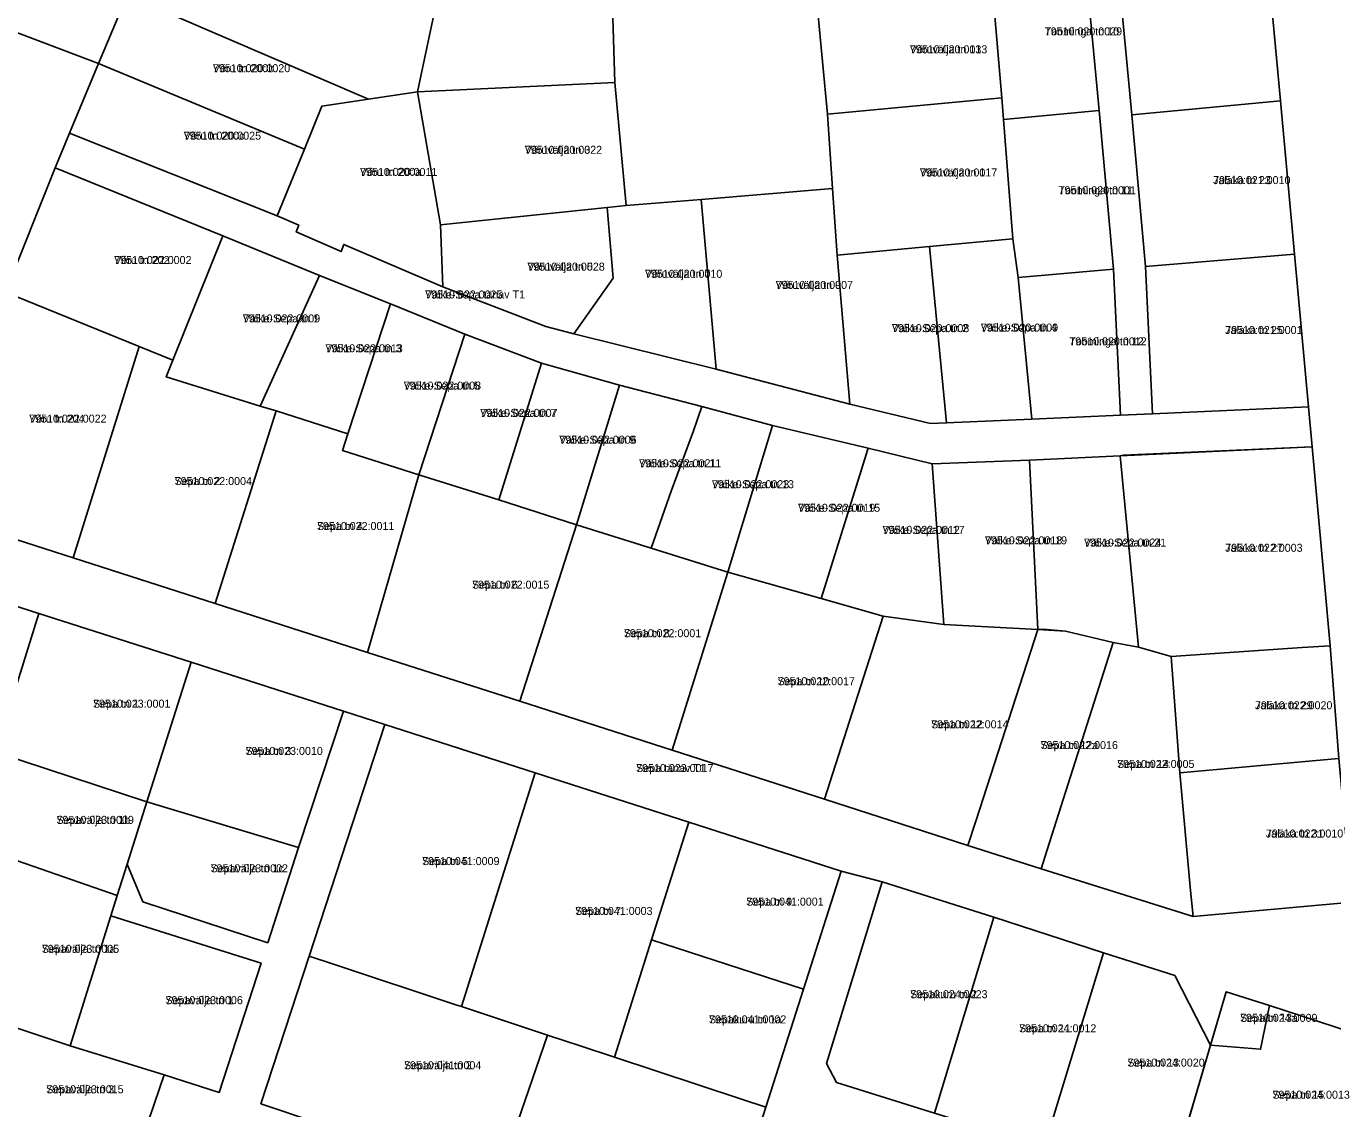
# Model space of a CAD drawing. Extents: x 643847 to 663718, y 6468443 to 6482775.
# Drawn here: x 659148.1 to 659393.1, y 6470944.7 to 6471147.7 of the extents above; entities that cross this region are included whole.
import ezdxf

# ---------------------------------------------------------------- set-up
doc = ezdxf.new("R2010")
doc.units = 0
for name, color, linetype in [('L_AADRESS', 7, 'Continuous'), ('PIIR', 7, 'Continuous'), ('TUNNUS', 7, 'Continuous')]:
    doc.layers.add(name, color=color, linetype=linetype)

msp = doc.modelspace()

# ---------------------------------------------------------------- linework, layer by layer
at = {"layer": 'PIIR'}
for points in [[(659341.82, 6471281.22), (659344.26, 6471253.81), (659347.37, 6471219.61), (659349.7, 6471192.1), (659352.5, 6471162.11), (659355.44, 6471131.04), (659357.98, 6471102.6), (659359.29, 6471075.01), (659353.29, 6471074.75), (659352, 6471102.11), (659349.29, 6471131.84), (659346.5, 6471161.7), (659344.95, 6471178.32), (659343.73, 6471191.56), (659341.19, 6471221.27), (659338.38, 6471251.03), (659335.78, 6471280.87)], [(659215.12, 6471272.69), (659207.74, 6471253.86), (659199.84, 6471234.85), (659192.92, 6471216.05), (659183.17, 6471191.52), (659179.27, 6471182.28), (659167.08, 6471153.51), (659161.74, 6471140.7), (659143.9, 6471147.43), (659146, 6471152.81), (659159.33, 6471183.88), (659165.84, 6471200.73), (659172.33, 6471217.52), (659190.04, 6471263.38)], [(659394.21, 6471010.38), (659392.61, 6471031.55), (659389.2, 6471068.83), (659388.52, 6471076.29), (659385.89, 6471104.93), (659383.27, 6471133.67), (659380.44, 6471164.64), (659377.72, 6471194.35), (659375.15, 6471222.47), (659372.07, 6471256.11), (659393.48, 6471257.44)], [(659296.51, 6471150.91), (659298.36, 6471131.19), (659299.32, 6471117.27), (659274.71, 6471115.16), (659260.61, 6471114.03), (659258.52, 6471137.09), (659257.67, 6471163.44)], [(659059.58, 6470932.21), (659070.24, 6470963.44), (659077.19, 6470983.79), (659085.91, 6471009.34), (659093.99, 6471033), (659101.62, 6471055.42), (659110.68, 6471064.49), (659132.41, 6471119.15), (659111.06, 6471126.27), (659112.87, 6471130.38), (659113.94, 6471132.87), (659134.67, 6471124.72), (659143.9, 6471147.43), (659161.74, 6471140.7), (659156.3, 6471127.64), (659153.58, 6471121.12), (659144.31, 6471097.84), (659128.09, 6471059.03), (659124.04, 6471046.08), (659115.81, 6471022.07), (659109.61, 6471003.78), (659099.59, 6470975.6), (659093.31, 6470956.47), (659086.53, 6470937.12)], [(659130.31, 6471056.6), (659156.94, 6471048.04), (659183.57, 6471039.44), (659212.14, 6471030.3), (659240.68, 6471021.12), (659269.23, 6471011.94), (659297.78, 6471002.75), (659324.71, 6470994.08), (659338.42, 6470989.73), (659366.89, 6470980.81), (659396.67, 6470983.46)], [(659399.57, 6470958.09), (659381.25, 6470964.1), (659373.12, 6470966.68), (659370.19, 6470956.69), (659363.46, 6470969.73), (659350.11, 6470973.96), (659329.56, 6470980.68), (659308.62, 6470987.26), (659300.94, 6470989.29), (659272.39, 6470998.46), (659243.57, 6471007.71), (659215.36, 6471016.77), (659207.64, 6471019.25), (659179.08, 6471028.43), (659150.5, 6471037.59), (659124.04, 6471046.08)], [(659281.07, 6470926.97), (659286.84, 6470945.06), (659293.89, 6470967.18), (659300.94, 6470989.29), (659308.62, 6470987.26), (659298.18, 6470953.21), (659300.07, 6470949.66), (659318.43, 6470943.89)]]:
    msp.add_lwpolyline(points, dxfattribs=at)
for points in [[(659179.27, 6471182.28), (659227.18, 6471162.23), (659221.51, 6471135.38), (659212.32, 6471134), (659167.08, 6471153.51)], [(659257.67, 6471163.44), (659258.52, 6471137.09), (659221.51, 6471135.38), (659227.18, 6471162.23)], [(659383.27, 6471133.67), (659355.44, 6471131.04), (659352.5, 6471162.11), (659380.44, 6471164.64)], [(659346.5, 6471161.7), (659349.29, 6471131.84), (659331.36, 6471130.16), (659331.04, 6471134.25), (659329.39, 6471153.98), (659328.88, 6471160.06)], [(659167.08, 6471153.51), (659212.32, 6471134), (659203.59, 6471132.69), (659200.33, 6471124.59), (659161.74, 6471140.7)], [(659296.51, 6471150.91), (659329.39, 6471153.98), (659331.04, 6471134.25), (659298.36, 6471131.19)], [(659161.74, 6471140.7), (659200.33, 6471124.59), (659195.19, 6471112.11), (659156.3, 6471127.64)], [(659260.61, 6471114.03), (659257.09, 6471113.66), (659225.8, 6471110.41), (659221.51, 6471135.38), (659258.52, 6471137.09)], [(659207.7, 6471106.76), (659207.2, 6471105.43), (659198.79, 6471109.11), (659199.26, 6471110.36), (659195.19, 6471112.11), (659200.33, 6471124.59), (659203.59, 6471132.69), (659212.32, 6471134), (659221.51, 6471135.38), (659225.8, 6471110.41), (659226.29, 6471098.81)], [(659298.36, 6471131.19), (659331.04, 6471134.25), (659331.36, 6471130.16), (659333.14, 6471107.83), (659317.52, 6471106.37), (659300.19, 6471104.75), (659299.32, 6471117.27)], [(659385.89, 6471104.93), (659357.98, 6471102.6), (659355.44, 6471131.04), (659383.27, 6471133.67)], [(659352, 6471102.11), (659334.1, 6471100.55), (659333.14, 6471107.83), (659331.36, 6471130.16), (659349.29, 6471131.84)], [(659185.02, 6471108.37), (659153.58, 6471121.12), (659156.3, 6471127.64), (659195.19, 6471112.11), (659199.26, 6471110.36), (659198.79, 6471109.11), (659207.2, 6471105.43), (659207.7, 6471106.76), (659226.29, 6471098.81), (659245.54, 6471091.41), (659250.81, 6471090.03), (659277.49, 6471083.38), (659302.59, 6471076.85), (659317.7, 6471073.17), (659320.7, 6471073.31), (659336.68, 6471074.01), (659353.29, 6471074.75), (659359.29, 6471075.01), (659388.52, 6471076.29), (659389.2, 6471068.83), (659353.81, 6471067.25), (659353.24, 6471067.14), (659336.25, 6471066.32), (659317.97, 6471065.62), (659305.99, 6471068.6), (659288.07, 6471072.81), (659274.79, 6471076.36), (659259.4, 6471080.38), (659244.77, 6471084.49), (659230.38, 6471089.97), (659216.47, 6471095.61), (659203.12, 6471100.95)], [(659153.58, 6471121.12), (659185.02, 6471108.37), (659175.65, 6471085.06), (659169.35, 6471087.6), (659144.31, 6471097.84)], [(659299.32, 6471117.27), (659300.19, 6471104.75), (659302.59, 6471076.85), (659277.49, 6471083.38), (659274.71, 6471115.16)], [(659250.81, 6471090.03), (659245.54, 6471091.41), (659226.29, 6471098.81), (659225.8, 6471110.41), (659257.09, 6471113.66), (659258.17, 6471100.45)], [(659250.81, 6471090.03), (659258.17, 6471100.45), (659257.09, 6471113.66), (659260.61, 6471114.03), (659274.71, 6471115.16), (659277.49, 6471083.38)], [(659203.12, 6471100.95), (659192.04, 6471076.45), (659174.41, 6471081.92), (659175.65, 6471085.06), (659185.02, 6471108.37)], [(659317.7, 6471073.17), (659302.59, 6471076.85), (659300.19, 6471104.75), (659317.52, 6471106.37), (659320.7, 6471073.31)], [(659320.7, 6471073.31), (659317.52, 6471106.37), (659333.14, 6471107.83), (659334.1, 6471100.55), (659336.68, 6471074.01)], [(659388.52, 6471076.29), (659359.29, 6471075.01), (659357.98, 6471102.6), (659385.89, 6471104.93)], [(659353.29, 6471074.75), (659336.68, 6471074.01), (659334.1, 6471100.55), (659352, 6471102.11)], [(659216.47, 6471095.61), (659208.46, 6471071.25), (659195.03, 6471075.6), (659192.04, 6471076.45), (659203.12, 6471100.95)], [(659144.31, 6471097.84), (659169.35, 6471087.6), (659156.94, 6471048.04), (659130.31, 6471056.6), (659128.09, 6471059.03)], [(659230.38, 6471089.97), (659221.77, 6471063.59), (659207.48, 6471068.13), (659208.46, 6471071.25), (659216.47, 6471095.61)], [(659244.77, 6471084.49), (659236.77, 6471058.91), (659221.77, 6471063.59), (659230.38, 6471089.97)], [(659156.94, 6471048.04), (659169.35, 6471087.6), (659175.65, 6471085.06), (659174.41, 6471081.92), (659192.04, 6471076.45), (659195.03, 6471075.6), (659183.57, 6471039.44)], [(659259.4, 6471080.38), (659251.31, 6471054.21), (659236.77, 6471058.91), (659244.77, 6471084.49)], [(659274.79, 6471076.36), (659273.27, 6471071.8), (659269.04, 6471060.54), (659265.32, 6471049.84), (659251.31, 6471054.21), (659259.4, 6471080.38)], [(659183.57, 6471039.44), (659195.03, 6471075.6), (659208.46, 6471071.25), (659207.48, 6471068.13), (659221.77, 6471063.59), (659212.14, 6471030.3)], [(659274.79, 6471076.36), (659288.07, 6471072.81), (659279.71, 6471045.36), (659265.32, 6471049.84), (659269.04, 6471060.54), (659273.27, 6471071.8)], [(659305.99, 6471068.6), (659297.18, 6471040.38), (659279.71, 6471045.36), (659288.07, 6471072.81)], [(659317.97, 6471065.62), (659320.19, 6471035.49), (659308.82, 6471037.05), (659297.18, 6471040.38), (659305.99, 6471068.6)], [(659336.25, 6471066.32), (659353.24, 6471067.14), (659356.68, 6471031.3), (659351.92, 6471032.12), (659342.96, 6471034.3), (659338.81, 6471034.63), (659337.82, 6471034.59)], [(659389.2, 6471068.83), (659392.61, 6471031.55), (659387.37, 6471031.2), (659362.78, 6471029.55), (659356.68, 6471031.3), (659353.24, 6471067.14)], [(659336.25, 6471066.32), (659337.82, 6471034.59), (659320.19, 6471035.49), (659317.97, 6471065.62)], [(659212.14, 6471030.3), (659221.77, 6471063.59), (659236.77, 6471058.91), (659251.31, 6471054.21), (659240.68, 6471021.12)], [(659240.68, 6471021.12), (659251.31, 6471054.21), (659265.32, 6471049.84), (659279.71, 6471045.36), (659269.23, 6471011.94)], [(659120.57, 6471020.56), (659115.81, 6471022.07), (659124.04, 6471046.08), (659150.5, 6471037.59), (659142.97, 6471013.48)], [(659269.23, 6471011.94), (659279.71, 6471045.36), (659297.18, 6471040.38), (659308.82, 6471037.05), (659297.78, 6471002.75)], [(659179.08, 6471028.43), (659170.8, 6471002.27), (659142.38, 6471011.57), (659142.97, 6471013.48), (659150.5, 6471037.59)], [(659297.78, 6471002.75), (659308.82, 6471037.05), (659320.19, 6471035.49), (659337.82, 6471034.6), (659326.25, 6470998.84), (659324.71, 6470994.08)], [(659324.71, 6470994.08), (659326.25, 6470998.84), (659337.82, 6471034.6), (659338.82, 6471034.54), (659342.96, 6471034.3), (659351.91, 6471032.15), (659339.94, 6470994.49), (659338.42, 6470989.73)], [(659338.42, 6470989.73), (659339.94, 6470994.49), (659351.92, 6471032.12), (659356.68, 6471031.3), (659362.78, 6471029.55), (659364.42, 6471007.72), (659366.45, 6470985.68), (659366.89, 6470980.81)], [(659394.21, 6471010.38), (659389.32, 6471009.94), (659364.42, 6471007.72), (659362.78, 6471029.55), (659387.37, 6471031.2), (659392.61, 6471031.55)], [(659207.64, 6471019.25), (659199.22, 6470993.71), (659170.8, 6471002.27), (659179.08, 6471028.43)], [(659199.22, 6470993.71), (659207.64, 6471019.25), (659215.36, 6471016.77), (659201.19, 6470973.35), (659192.16, 6470945.68), (659202.59, 6470942.2), (659196.07, 6470923.07), (659189.56, 6470904), (659183.08, 6470884.91), (659175.18, 6470861.72), (659147.36, 6470870.74), (659155.01, 6470894.04), (659161.25, 6470913.03), (659167.56, 6470932.23), (659174.01, 6470951.1), (659184.35, 6470947.81), (659192.19, 6470972.02), (659164.03, 6470980.9), (659165.23, 6470984.72), (659167.11, 6470990.59), (659170.02, 6470983.54), (659193.43, 6470975.86)], [(659243.57, 6471007.71), (659229.76, 6470963.89), (659228.71, 6470964.23), (659205.94, 6470971.78), (659201.19, 6470973.35), (659215.36, 6471016.77)], [(659170.8, 6471002.27), (659167.11, 6470990.59), (659165.23, 6470984.72), (659146.52, 6470991.23), (659137.04, 6470994.45), (659142.38, 6471011.57)], [(659396.67, 6470983.46), (659366.89, 6470980.81), (659366.45, 6470985.68), (659364.42, 6471007.72), (659389.32, 6471009.94), (659394.21, 6471010.38)], [(659272.39, 6470998.46), (659265.41, 6470976.44), (659258.44, 6470954.42), (659252.17, 6470956.5), (659245.89, 6470958.55), (659229.76, 6470963.89), (659243.57, 6471007.71)], [(659193.43, 6470975.86), (659170.02, 6470983.54), (659167.11, 6470990.59), (659170.8, 6471002.27), (659199.22, 6470993.71)], [(659300.94, 6470989.29), (659293.89, 6470967.18), (659265.41, 6470976.44), (659272.39, 6470998.46)], [(659164.03, 6470980.9), (659156.39, 6470956.54), (659136.93, 6470963.06), (659146.52, 6470991.23), (659165.23, 6470984.72)], [(659308.62, 6470987.26), (659329.56, 6470980.68), (659318.43, 6470943.89), (659300.07, 6470949.66), (659298.18, 6470953.21)], [(659184.35, 6470947.81), (659174.01, 6470951.1), (659156.39, 6470956.54), (659164.03, 6470980.9), (659192.19, 6470972.02)], [(659350.11, 6470973.96), (659338.97, 6470937.57), (659318.43, 6470943.89), (659329.56, 6470980.68)], [(659286.84, 6470945.06), (659282.09, 6470946.63), (659258.44, 6470954.42), (659265.41, 6470976.44), (659293.89, 6470967.18)], [(659363.46, 6470969.73), (659370.19, 6470956.69), (659362.45, 6470930.34), (659338.97, 6470937.57), (659350.11, 6470973.96)], [(659201.19, 6470973.35), (659205.94, 6470971.78), (659228.71, 6470964.23), (659229.76, 6470963.89), (659245.89, 6470958.55), (659239.59, 6470940.16), (659236.17, 6470930.95), (659207.34, 6470940.63), (659202.59, 6470942.2), (659192.16, 6470945.68)], [(659381.25, 6470964.1), (659379.57, 6470955.9), (659370.19, 6470956.69), (659373.12, 6470966.68)], [(659399.57, 6470958.09), (659402.04, 6470931.82), (659373.44, 6470928.31), (659361.53, 6470927.24), (659370.19, 6470956.69), (659379.57, 6470955.9), (659381.25, 6470964.1)], [(659167.56, 6470932.23), (659129.77, 6470944.39), (659136.93, 6470963.06), (659156.39, 6470956.54), (659174.01, 6470951.1)], [(659281.07, 6470926.97), (659270.5, 6470930.36), (659252.1, 6470936.2), (659239.59, 6470940.16), (659245.89, 6470958.55), (659252.17, 6470956.5), (659258.44, 6470954.42), (659282.09, 6470946.63), (659286.84, 6470945.06)]]:
    msp.add_lwpolyline(points, close=True, dxfattribs=at)

# ---------------------------------------------------------------- texts
at = {"layer": 'L_AADRESS'}
for s, p in [('Toominga tn 10', (659339.09, 6471145.95)), ('Võruvälja tn 13', (659313.82, 6471142.59)), ('Võru tn 200b', (659183.15, 6471139.05)), ('Võru tn 200c', (659177.69, 6471126.4)), ('Võruvälja tn 3', (659241.62, 6471123.75)), ('Võru tn 200a', (659210.74, 6471119.61)), ('Võruvälja tn 11', (659315.69, 6471119.5)), ('Jalaka tn 23', (659370.66, 6471118.07)), ('Toominga tn 11', (659341.68, 6471116.17)), ('Võru tn 202', (659164.65, 6471103.09)), ('Võruvälja tn 5', (659242.11, 6471101.85)), ('Võruvälja tn 7', (659264.15, 6471100.51)), ('Võruvälja tn 9', (659288.65, 6471098.42)), ('Väike-Sepa tänav T1', (659222.94, 6471096.63)), ('Väike-Sepa tn 1', (659188.76, 6471092.15)), ('Väike-Sepa tn 2', (659310.45, 6471090.32)), ('Väike-Sepa tn 4', (659327.1, 6471090.43)), ('Jalaka tn 25', (659372.92, 6471089.97)), ('Toominga tn 12', (659343.7, 6471087.85)), ('Väike-Sepa tn 3', (659204.25, 6471086.55)), ('Väike-Sepa tn 5', (659218.93, 6471079.55)), ('Võru tn 204', (659148.72, 6471073.36)), ('Väike-Sepa tn 7', (659233.27, 6471074.44)), ('Väike-Sepa tn 9', (659248.09, 6471069.41)), ('Väike-Sepa tn 11', (659263.05, 6471064.99)), ('Sepa tn 2', (659175.98, 6471061.66)), ('Väike-Sepa tn 13', (659276.7, 6471061.07)), ('Väike-Sepa tn 15', (659292.85, 6471056.65)), ('Sepa tn 4', (659202.67, 6471053.23)), ('Väike-Sepa tn 17', (659308.68, 6471052.51)), ('Väike-Sepa tn 19', (659327.89, 6471050.55)), ('Väike-Sepa tn 21', (659346.46, 6471050.13)), ('Jalaka tn 27', (659372.93, 6471049.15)), ('Sepa tn 6', (659231.73, 6471042.24)), ('Sepa tn 8', (659260.2, 6471033.14)), ('Sepa tn 10', (659289.02, 6471024.14)), ('Sepa tn 1', (659160.69, 6471019.93)), ('Jalaka tn 29', (659378.52, 6471019.63)), ('Sepa tn 12', (659317.8, 6471016.06)), ('Sepa tn 12a', (659338.31, 6471012.17)), ('Sepa tn 3', (659189.26, 6471011.07)), ('Sepa tänav T1', (659262.5, 6471007.86)), ('Sepa tn 14', (659352.66, 6471008.63)), ('Sepavälja tn 1b', (659153.84, 6470998.15)), ('Jalaka tn 31', (659380.55, 6470995.59)), ('Sepa tn 5', (659222.38, 6470990.42)), ('Sepavälja tn 1c', (659182.73, 6470989.07)), ('Sepa tn 9', (659283.15, 6470982.82)), ('Sepa tn 7', (659251.07, 6470981.08)), ('Sepavälja tn 1a', (659151.08, 6470973.98)), ('Sepakuru tn 2', (659313.87, 6470965.47)), ('Sepavälja tn 1', (659174.27, 6470964.35)), ('Sepakuru tn 1a', (659276.14, 6470960.75)), ('Sepa tn 13a', (659375.72, 6470961.04)), ('Sepa tn 11', (659334.27, 6470959.08)), ('Sepavälja tn 2', (659218.98, 6470952.15)), ('Sepa tn 13', (659354.58, 6470952.65)), ('Sepavälja tn 3', (659151.92, 6470947.65)), ('Sepa tn 15', (659381.79, 6470946.63))]:
    msp.add_text(s, height=1.5, dxfattribs=at).set_placement(p)
at = {"layer": 'TUNNUS'}
for s, p in [('79510:020:0029', (659339.09, 6471145.95)), ('79510:020:0013', (659313.82, 6471142.59)), ('79510:020:0020', (659183.15, 6471139.05)), ('79510:020:0025', (659177.69, 6471126.4)), ('79510:020:0022', (659241.62, 6471123.75)), ('79510:020:0011', (659210.74, 6471119.61)), ('79510:020:0017', (659315.69, 6471119.5)), ('79510:021:0010', (659370.66, 6471118.07)), ('79510:020:0001', (659341.68, 6471116.17)), ('79510:022:0002', (659164.65, 6471103.09)), ('79510:020:0028', (659242.11, 6471101.85)), ('79510:020:0010', (659264.15, 6471100.51)), ('79510:020:0007', (659288.65, 6471098.42)), ('79510:022:0025', (659222.94, 6471096.63)), ('79510:022:0009', (659188.76, 6471092.15)), ('79510:020:0008', (659310.45, 6471090.32)), ('79510:020:0009', (659327.1, 6471090.43)), ('79510:021:0001', (659372.92, 6471089.97)), ('79510:020:0012', (659343.7, 6471087.85)), ('79510:022:0013', (659204.25, 6471086.55)), ('79510:022:0008', (659218.93, 6471079.55)), ('79510:022:0022', (659148.72, 6471073.36)), ('79510:022:0007', (659233.27, 6471074.44)), ('79510:022:0006', (659248.09, 6471069.41)), ('79510:022:0021', (659263.05, 6471064.99)), ('79510:022:0004', (659175.98, 6471061.66)), ('79510:022:0023', (659276.7, 6471061.07)), ('79510:022:0019', (659292.85, 6471056.65)), ('79510:022:0011', (659202.67, 6471053.23)), ('79510:022:0012', (659308.68, 6471052.51)), ('79510:022:0018', (659327.89, 6471050.55)), ('79510:022:0024', (659346.46, 6471050.13)), ('79510:022:0003', (659372.93, 6471049.15)), ('79510:022:0015', (659231.73, 6471042.24)), ('79510:022:0001', (659260.2, 6471033.14)), ('79510:022:0017', (659289.02, 6471024.14)), ('79510:023:0001', (659160.69, 6471019.93)), ('79510:022:0020', (659378.52, 6471019.63)), ('79510:022:0014', (659317.8, 6471016.06)), ('79510:022:0016', (659338.31, 6471012.17)), ('79510:023:0010', (659189.26, 6471011.07)), ('79510:023:0017', (659262.5, 6471007.86)), ('79510:022:0005', (659352.66, 6471008.63)), ('79510:023:0009', (659153.84, 6470998.15)), ('79510:022:0010', (659380.55, 6470995.59)), ('79510:041:0009', (659222.38, 6470990.42)), ('79510:023:0002', (659182.73, 6470989.07)), ('79510:041:0001', (659283.15, 6470982.82)), ('79510:041:0003', (659251.07, 6470981.08)), ('79510:023:0005', (659151.08, 6470973.98)), ('79510:024:0023', (659313.87, 6470965.47)), ('79510:023:0006', (659174.27, 6470964.35)), ('79510:041:0002', (659276.14, 6470960.75)), ('79510:024:0009', (659375.72, 6470961.04)), ('79510:024:0012', (659334.27, 6470959.08)), ('79510:041:0004', (659218.98, 6470952.15)), ('79510:024:0020', (659354.58, 6470952.65)), ('79510:023:0015', (659151.92, 6470947.65)), ('79510:024:0013', (659381.79, 6470946.63))]:
    msp.add_text(s, height=1.5, dxfattribs=at).set_placement(p)

doc.saveas('drawing.dxf')
